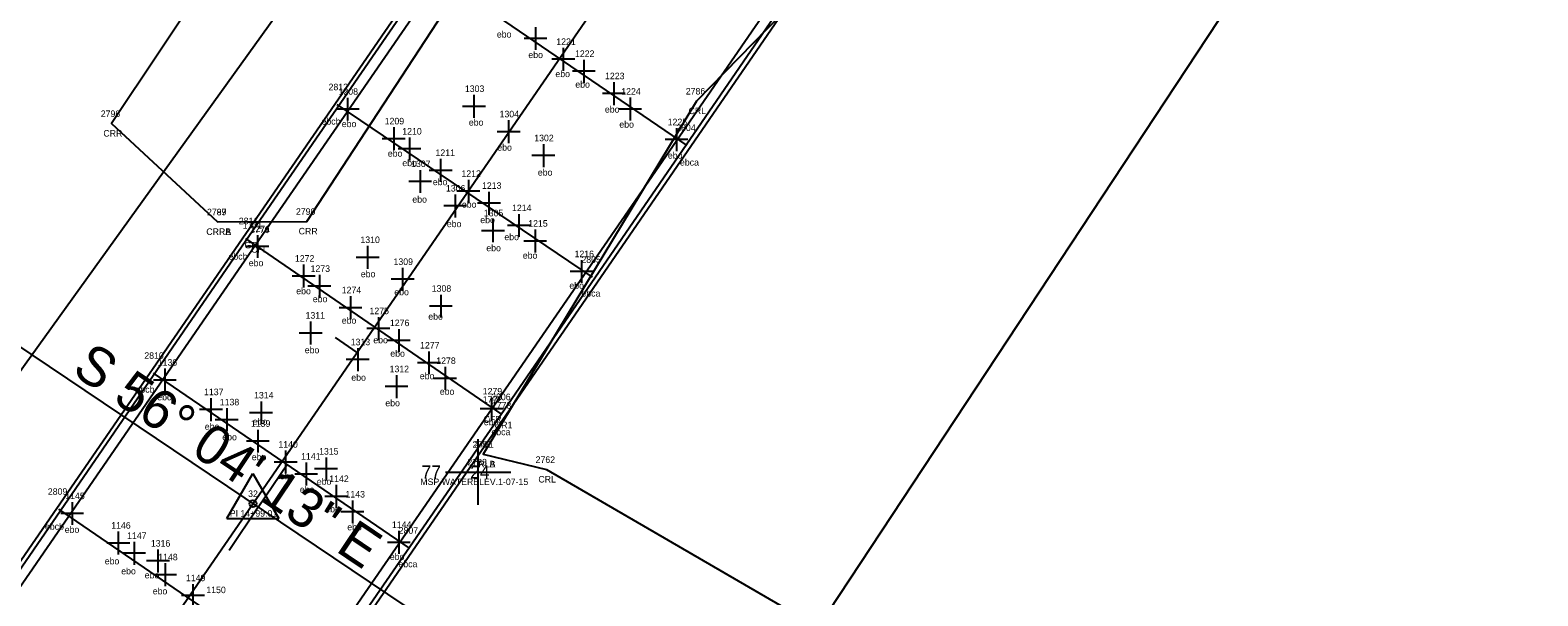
# Model space of a CAD drawing. Extents: x 2266664 to 2272542, y 716533 to 724777.
# Drawn here: x 2269061 to 2269291.5, y 720003.3 to 720089.8 of the extents above; entities that cross this region are included whole.
import ezdxf

# ---------------------------------------------------------------- set-up
doc = ezdxf.new("R2010")
doc.units = 0
for name, color, linetype in [('RD_EX_Bridge', 7, 'Continuous'), ('RD_EX_Conc', 7, 'Continuous'), ('RD_EX_Conc_txCode', 7, 'Continuous'), ('RD_EX_GuardRail', 7, 'Continuous'), ('RD_EX_GuardRail_txCode', 7, 'Continuous'), ('RD_EX_H2O', 7, 'Continuous'), ('RD_EX_H2O_txCode', 7, 'Continuous'), ('RD_EX_Misc', 7, 'Continuous'), ('RD_EX_Misc_txCode', 7, 'Continuous'), ('RD_EX_VEG', 7, 'Continuous'), ('RD_HC_Cl', 7, 'Continuous'), ('RD_HC_Data', 7, 'Continuous'), ('RD_HC_Data_Tic', 7, 'Continuous'), ('RD_HC_txCode', 7, 'Continuous'), ('RD_SMD_Locator', 7, 'Continuous')]:
    doc.layers.add(name, color=color, linetype=linetype)

msp = doc.modelspace()

# ---------------------------------------------------------------- linework, layer by layer
at = {"layer": 'RD_EX_Bridge'}
msp.add_lwpolyline([(2269005.71, 719844.75), (2269233.07, 720175.43), (2269193.18, 720202.86), (2268965.85, 719872.44), (2269005.71, 719844.75)], dxfattribs=at)
at = {"layer": 'RD_EX_Conc'}
for points in [[(2268967.59, 719871.21), (2269010.36, 719933.37), (2269052.74, 719994.95), (2269096, 720057.76), (2269138.05, 720118.85), (2269194.93, 720201.62)], [(2269004.04, 719846.24), (2269046.75, 719908.42), (2269089.1, 719970.17), (2269131.56, 720031.81), (2269174.47, 720094.11), (2269231.14, 720176.62)]]:
    msp.add_lwpolyline(points, dxfattribs=at)
at = {"layer": 'RD_EX_GuardRail'}
for points in [[(2268966.72, 719781.34), (2268981.11, 719807.65), (2269004.56, 719845.55), (2269006.56, 719847.08), (2269048.04, 719907.43), (2269090.37, 719969.18), (2269132.94, 720030.91), (2269175.81, 720093.43), (2269231.32, 720174.06), (2269253.93, 720204.36), (2269271.7, 720223.93)], [(2268919.97, 719814.14), (2268926.75, 719820.52), (2268951.58, 719851.69), (2268966.29, 719871.68), (2268967.47, 719873.87), (2269009.19, 719934.42), (2269051.44, 719995.68), (2269094.56, 720058.42), (2269136.79, 720119.9), (2269193.57, 720202.38)]]:
    msp.add_lwpolyline(points, dxfattribs=at)
at = {"layer": 'RD_EX_H2O'}
for points in [[(2269172.99, 720195.51), (2269184.44, 720188.83), (2269212.95, 720153.63), (2269214.79, 720144.82), (2269223.14, 720135.04), (2269221.7, 720125.29), (2269214.42, 720123.45), (2269202.97, 720124.92), (2269182.34, 720098.94), (2269162.9, 720078.96), (2269130.27, 720024.93)], [(2269089.67, 720060.48), (2269103.31, 720060.56), (2269128.67, 720099.37), (2269142.41, 720139.49), (2269136.61, 720156.25), (2269131.18, 720158.45), (2269103.12, 720119.97), (2269073.45, 720075.52), (2269089.67, 720060.48)], [(2269130.27, 720024.93), (2269139.94, 720022.61), (2269202.7, 719986.16), (2269249.42, 719942.61), (2269307.1, 719885.4), (2269359.22, 719846.16), (2269432.06, 719783.5), (2269460, 719761.58), (2269521.39, 719745.69)]]:
    msp.add_lwpolyline(points, dxfattribs=at)
at = {"layer": 'RD_EX_Misc'}
for p, q in [((2269161.46, 720072.18), (2269122.16, 720099.01)), ((2269138.27, 720090.28), (2269138.27, 720086.78)), ((2269140.02, 720088.53), (2269136.52, 720088.53)), ((2269142.51, 720087.09), (2269142.51, 720083.59)), ((2269144.26, 720085.34), (2269140.76, 720085.34)), ((2269147.41, 720083.51), (2269143.91, 720083.51)), ((2269145.66, 720085.26), (2269145.66, 720081.76)), ((2269150.25, 720081.85), (2269150.25, 720078.35)), ((2269109.54, 720079.47), (2269109.54, 720075.97)), ((2269128.85, 720079.9), (2269128.85, 720076.4)), ((2269152, 720080.1), (2269148.5, 720080.1)), ((2269152.73, 720079.48), (2269152.73, 720075.98)), ((2269111.29, 720077.72), (2269107.79, 720077.72)), ((2269146.96, 720052), (2269107.97, 720078.41)), ((2269130.6, 720078.15), (2269127.1, 720078.15)), ((2269154.48, 720077.73), (2269150.98, 720077.73)), ((2269116.6, 720074.95), (2269116.6, 720071.45)), ((2269135.91, 720074.27), (2269132.41, 720074.27)), ((2269134.16, 720076.02), (2269134.16, 720072.52)), ((2269159.83, 720074.81), (2269159.83, 720071.31)), ((2269118.35, 720073.2), (2269114.85, 720073.2)), ((2269120.75, 720071.63), (2269117.25, 720071.63)), ((2269119, 720073.38), (2269119, 720069.88)), ((2269139.47, 720072.36), (2269139.47, 720068.86)), ((2269161.58, 720073.06), (2269158.08, 720073.06)), ((2269123.76, 720070.1), (2269123.76, 720066.6)), ((2269141.22, 720070.61), (2269137.72, 720070.61)), ((2269120.63, 720068.41), (2269120.63, 720064.91)), ((2269125.51, 720068.35), (2269122.01, 720068.35)), ((2269128.01, 720066.91), (2269128.01, 720063.41)), ((2269122.38, 720066.66), (2269118.88, 720066.66)), ((2269125.99, 720064.67), (2269125.99, 720061.17)), ((2269129.76, 720065.16), (2269126.26, 720065.16)), ((2269131.16, 720065.08), (2269131.16, 720061.58)), ((2269127.74, 720062.92), (2269124.24, 720062.92)), ((2269132.91, 720063.33), (2269129.41, 720063.33)), ((2269131.76, 720060.88), (2269131.76, 720057.38)), ((2269135.74, 720061.67), (2269135.74, 720058.17)), ((2269133.19, 720031), (2269093.98, 720057.92)), ((2269095.77, 720058.46), (2269095.77, 720054.96)), ((2269133.51, 720059.13), (2269130.01, 720059.13)), ((2269137.49, 720059.92), (2269133.99, 720059.92)), ((2269138.22, 720059.29), (2269138.22, 720055.79)), ((2269097.52, 720056.71), (2269094.02, 720056.71)), ((2269112.6, 720056.79), (2269112.6, 720053.29)), ((2269139.97, 720057.54), (2269136.47, 720057.54)), ((2269102.82, 720053.94), (2269102.82, 720050.44)), ((2269114.35, 720055.04), (2269110.85, 720055.04)), ((2269117.95, 720053.44), (2269117.95, 720049.94)), ((2269145.32, 720054.63), (2269145.32, 720051.13)), ((2269104.57, 720052.19), (2269101.07, 720052.19)), ((2269105.23, 720052.38), (2269105.23, 720048.88)), ((2269119.7, 720051.69), (2269116.2, 720051.69)), ((2269147.07, 720052.88), (2269143.57, 720052.88)), ((2269106.98, 720050.63), (2269103.48, 720050.63)), ((2269109.99, 720049.1), (2269109.99, 720045.6)), ((2269123.8, 720049.34), (2269123.8, 720045.84)), ((2269111.74, 720047.35), (2269108.24, 720047.35)), ((2269125.55, 720047.59), (2269122.05, 720047.59)), ((2269103.89, 720045.23), (2269103.89, 720041.73)), ((2269115.99, 720044.16), (2269112.49, 720044.16)), ((2269114.24, 720045.91), (2269114.24, 720042.41)), ((2269117.38, 720044.08), (2269117.38, 720040.58)), ((2269105.64, 720043.48), (2269102.14, 720043.48)), ((2269119.13, 720042.33), (2269115.63, 720042.33)), ((2269112.84, 720039.41), (2269109.34, 720039.41)), ((2269111.09, 720041.16), (2269111.09, 720037.66)), ((2269121.97, 720040.66), (2269121.97, 720037.16)), ((2269119.02, 720010.58), (2269079.84, 720037.33)), ((2269081.6, 720038.04), (2269081.6, 720034.54)), ((2269117.02, 720037.03), (2269117.02, 720033.53)), ((2269123.72, 720038.91), (2269120.22, 720038.91)), ((2269124.45, 720038.29), (2269124.45, 720034.79)), ((2269083.35, 720036.29), (2269079.85, 720036.29)), ((2269118.77, 720035.28), (2269115.27, 720035.28)), ((2269126.2, 720036.54), (2269122.7, 720036.54)), ((2269088.65, 720033.52), (2269088.65, 720030.02)), ((2269096.3, 720033.02), (2269096.3, 720029.52)), ((2269131.55, 720033.63), (2269131.55, 720030.13)), ((2269090.4, 720031.77), (2269086.9, 720031.77)), ((2269092.81, 720030.21), (2269089.31, 720030.21)), ((2269091.06, 720031.96), (2269091.06, 720028.46)), ((2269098.05, 720031.27), (2269094.55, 720031.27)), ((2269133.3, 720031.88), (2269129.8, 720031.88)), ((2269095.82, 720028.68), (2269095.82, 720025.18)), ((2269097.57, 720026.93), (2269094.07, 720026.93)), ((2269100.07, 720025.49), (2269100.07, 720021.99)), ((2269129.5, 720017.22), (2269129.5, 720027.22)), ((2269101.82, 720023.74), (2269098.32, 720023.74)), ((2269103.21, 720023.66), (2269103.21, 720020.16)), ((2269106.24, 720024.43), (2269106.24, 720020.93)), ((2269104.96, 720021.91), (2269101.46, 720021.91)), ((2269107.99, 720022.68), (2269104.49, 720022.68)), ((2269124.5, 720022.22), (2269134.5, 720022.22)), ((2269109.55, 720018.49), (2269106.05, 720018.49)), ((2269107.8, 720020.24), (2269107.8, 720016.74)), ((2269104.26, 719989.95), (2269065.38, 720016.53)), ((2269067.43, 720017.62), (2269067.43, 720014.12)), ((2269110.28, 720017.87), (2269110.28, 720014.37)), ((2269069.18, 720015.87), (2269065.68, 720015.87)), ((2269112.03, 720016.12), (2269108.53, 720016.12)), ((2269074.48, 720013.1), (2269074.48, 720009.6)), ((2269117.38, 720013.21), (2269117.38, 720009.71)), ((2269076.23, 720011.35), (2269072.73, 720011.35)), ((2269078.64, 720009.79), (2269075.14, 720009.79)), ((2269076.89, 720011.54), (2269076.89, 720008.04)), ((2269080.55, 720010.36), (2269080.55, 720006.86)), ((2269119.13, 720011.46), (2269115.63, 720011.46)), ((2269082.3, 720008.61), (2269078.8, 720008.61)), ((2269081.65, 720008.26), (2269081.65, 720004.76)), ((2269083.4, 720006.51), (2269079.9, 720006.51)), ((2269085.9, 720005.07), (2269085.9, 720001.57)), ((2269087.65, 720003.32), (2269084.15, 720003.32))]:
    msp.add_line(p, q, dxfattribs=at)
at = {"layer": 'RD_EX_VEG'}
for points in [[(2268819.78, 719716.8), (2268871.54, 719776.21), (2269193.85, 720224.65), (2269408.57, 720538.5), (2269589.67, 720791.77), (2270047.56, 721479.8), (2270363.13, 721951.09), (2270746.65, 722498.38), (2270919.94, 722752.82), (2271017.26, 722923.37)], [(2268988.31, 719705.64), (2269316.7, 720203.55), (2269323.19, 720195.95)]]:
    msp.add_lwpolyline(points, dxfattribs=at)
at = {"layer": 'RD_HC_Cl'}
for p, q in [((2267342.91, 717471.2), (2272360.46, 724762.59)), ((2269054.71, 720044.54), (2269123.76, 719998.09))]:
    msp.add_line(p, q, dxfattribs=at)
at = {"layer": 'RD_HC_Data'}
for p, q in [((2269091.09, 720015.1), (2269095.07, 720021.98)), ((2269095.07, 720021.98), (2269099.03, 720015.1)), ((2269091.09, 720015.1), (2269099.03, 720015.1))]:
    msp.add_line(p, q, dxfattribs=at)
msp.add_circle((2269095.06, 720017.39), 0.529, dxfattribs=at)
at = {"layer": 'RD_HC_Data_Tic'}
for p, q in [((2269110.98, 720040.52), (2269107.68, 720042.79)), ((2269095.89, 720016.84), (2269100.35, 720023.47)), ((2269095.89, 720016.84), (2269091.42, 720010.2))]:
    msp.add_line(p, q, dxfattribs=at)
at = {"layer": 'RD_SMD_Locator'}
for centre in [(2269162.9, 720078.96), (2269073.45, 720075.52), (2269089.67, 720060.48), (2269089.67, 720060.48), (2269103.31, 720060.56), (2269094.56, 720058.42), (2269096, 720057.76), (2269131.56, 720031.81), (2269132.94, 720030.91), (2269130.27, 720024.93), (2269130.27, 720024.93), (2269139.94, 720022.61), (2269095.06, 720017.39)]:
    msp.add_circle(centre, 0.001, dxfattribs=at)

# ---------------------------------------------------------------- texts
at = {"layer": 'RD_EX_Conc_txCode'}
for s, p in [('1770', (2269094.62, 720058.76)), ('CFL', (2269094.8, 720055.76)), ('1772', (2269130.22, 720032.81)), ('CFR', (2269130.33, 720029.81))]:
    msp.add_text(s, height=1, dxfattribs=at).set_placement(p)
at = {"layer": 'RD_EX_GuardRail_txCode'}
for s, p in [('1771', (2269093.5, 720059.42)), ('GR', (2269093.78, 720056.42)), ('1773', (2269131.59, 720031.91)), ('GR1', (2269131.99, 720028.91))]:
    msp.add_text(s, height=1, dxfattribs=at).set_placement(p)
at = {"layer": 'RD_EX_H2O_txCode'}
for s, p in [('2786', (2269161.25, 720079.96)), ('2796', (2269071.8, 720076.52)), ('CRL', (2269161.67, 720076.96)), ('CRR', (2269072.2, 720073.52)), ('2789', (2269088.04, 720061.48)), ('2797', (2269088.04, 720061.48)), ('2790', (2269101.64, 720061.56)), ('CRRA', (2269087.93, 720058.48)), ('CRRB', (2269087.95, 720058.48)), ('CRR', (2269102.06, 720058.56)), ('2787', (2269128.64, 720025.93)), ('2761', (2269128.9, 720025.93)), ('CRLA', (2269128.55, 720022.93)), ('CRLB', (2269128.57, 720022.93)), ('2762', (2269138.29, 720023.61)), ('CRL', (2269138.71, 720020.61))]:
    msp.add_text(s, height=1, dxfattribs=at).set_placement(p)
at = {"layer": 'RD_EX_Misc_txCode'}
for s, height, p in [('ebo', 1, (2269132.36, 720088.67)), ('1221', 1, (2269141.45, 720087.54)), ('ebo', 1, (2269137.18, 720085.53)), ('1222', 1, (2269144.31, 720085.71)), ('ebo', 1, (2269141.31, 720082.62)), ('1223', 1, (2269148.9, 720082.3)), ('2812', 1, (2269106.63, 720080.61)), ('1208', 1, (2269108.16, 720079.92)), ('1303', 1, (2269127.47, 720080.35)), ('ebo', 1, (2269144.36, 720081.01)), ('1224', 1, (2269151.38, 720079.93)), ('ebcb', 1, (2269105.55, 720075.36)), ('1209', 1, (2269115.21, 720075.39)), ('ebo', 1, (2269128.08, 720075.2)), ('1304', 1, (2269132.78, 720076.47)), ('ebo', 1, (2269148.88, 720077.19)), ('1225', 1, (2269158.48, 720075.26)), ('ebo', 1, (2269108.65, 720074.97)), ('1210', 1, (2269117.9, 720073.83)), ('1302', 1, (2269138.08, 720072.81)), ('ebo', 1, (2269151.09, 720074.89)), ('2804', 1, (2269159.79, 720074.38)), ('1211', 1, (2269122.98, 720070.55)), ('ebo', 1, (2269132.43, 720071.37)), ('ebo', 1, (2269115.69, 720070.45)), ('ebo', 1, (2269117.91, 720069)), ('1307', 1, (2269119.25, 720068.86)), ('ebo', 1, (2269158.51, 720070.15)), ('ebca', 1, (2269160.36, 720069.09)), ('ebo', 1, (2269122.57, 720066.09)), ('1212', 1, (2269126.95, 720067.36)), ('ebo', 1, (2269138.63, 720067.55)), ('1306', 1, (2269124.58, 720065.12)), ('1213', 1, (2269130.09, 720065.53)), ('ebo', 1, (2269119.44, 720063.42)), ('ebo', 1, (2269127.01, 720062.65)), ('1305', 1, (2269130.37, 720061.33)), ('1214', 1, (2269134.68, 720062.12)), ('2811', 1, (2269092.91, 720060.12)), ('ebo', 1, (2269124.71, 720059.67)), ('ebo', 1, (2269129.83, 720060.28)), ('1215', 1, (2269137.16, 720059.74)), ('1271', 1, (2269094.71, 720058.91)), ('1310', 1, (2269111.5, 720057.24)), ('ebo', 1, (2269133.51, 720057.68)), ('ebcb', 1, (2269091.33, 720054.7)), ('1272', 1, (2269101.48, 720054.39)), ('ebo', 1, (2269130.75, 720055.99)), ('ebo', 1, (2269136.33, 720054.85)), ('1216', 1, (2269144.24, 720055.08)), ('ebo', 1, (2269094.43, 720053.7)), ('1273', 1, (2269103.88, 720052.83)), ('1309', 1, (2269116.56, 720053.89)), ('2805', 1, (2269145.29, 720054.2)), ('ebo', 1, (2269111.56, 720052.01)), ('1308', 1, (2269122.41, 720049.79)), ('ebo', 1, (2269143.45, 720050.25)), ('ebo', 1, (2269101.69, 720049.41)), ('ebo', 1, (2269104.22, 720048.19)), ('1274', 1, (2269108.64, 720049.55)), ('ebo', 1, (2269116.68, 720049.26)), ('ebca', 1, (2269145.29, 720049.05)), ('1311', 1, (2269103.11, 720045.68)), ('1275', 1, (2269112.89, 720046.36)), ('ebo', 1, (2269121.88, 720045.51)), ('ebo', 1, (2269108.65, 720044.9)), ('1276', 1, (2269116.01, 720044.53)), ('1313', 1, (2269110.02, 720041.61)), ('ebo', 1, (2269113.47, 720041.91)), ('1277', 1, (2269120.62, 720041.11)), ('2810', 1, (2269078.46, 720039.53)), ('1136', 1, (2269080.51, 720038.49)), ('ebo', 1, (2269102.99, 720040.38)), ('ebo', 1, (2269116.07, 720039.85)), ('1278', 1, (2269123.1, 720038.74)), ('ebo', 1, (2269110.11, 720036.18)), ('1312', 1, (2269115.96, 720037.48)), ('ebo', 1, (2269120.58, 720036.41)), ('ebcb', 1, (2269077.11, 720034.35)), ('1137', 1, (2269087.59, 720033.97)), ('ebo', 1, (2269123.64, 720034.03)), ('1279', 1, (2269130.2, 720034.08)), ('ebo', 1, (2269080.44, 720033.19)), ('1138', 1, (2269090, 720032.41)), ('1314', 1, (2269095.24, 720033.47)), ('ebo', 1, (2269115.31, 720032.27)), ('2806', 1, (2269131.49, 720033.2)), ('1139', 1, (2269094.76, 720029.13)), ('ebo', 1, (2269095.04, 720029.44)), ('ebo', 1, (2269130.37, 720029.37)), ('ebo', 1, (2269087.7, 720028.68)), ('ebo', 1, (2269090.38, 720027.07)), ('ebca', 1, (2269131.53, 720027.85)), ('1140', 1, (2269098.96, 720025.94)), ('1315', 1, (2269105.18, 720024.88)), ('ebo', 1, (2269094.89, 720024.01)), ('1141', 1, (2269102.43, 720024.11)), ('77      24', 2, (2269120.85, 720021.22)), ('2788', 1, (2269127.87, 720023.22)), ('ebo', 1, (2269099.17, 720021.1)), ('ebo', 1, (2269104.83, 720020.26)), ('1142', 1, (2269106.74, 720020.69)), ('MSP WATERELEV.1-07-15', 1, (2269120.66, 720020.22)), ('2809', 1, (2269063.71, 720018.73)), ('1145', 1, (2269066.37, 720018.07)), ('ebo', 1, (2269102.23, 720019.04)), ('1143', 1, (2269109.22, 720018.32)), ('ebo', 1, (2269106.13, 720016.05)), ('ebcb', 1, (2269063.27, 720013.39)), ('ebo', 1, (2269066.29, 720012.91)), ('1146', 1, (2269073.4, 720013.55)), ('ebo', 1, (2269109.49, 720013.3)), ('1144', 1, (2269116.32, 720013.66)), ('1147', 1, (2269075.83, 720011.99)), ('1316', 1, (2269079.46, 720010.81)), ('2807', 1, (2269117.35, 720012.78)), ('1148', 1, (2269080.59, 720008.71)), ('ebo', 1, (2269115.99, 720008.78)), ('ebo', 1, (2269072.41, 720008.09)), ('ebo', 1, (2269074.93, 720006.56)), ('ebo', 1, (2269078.52, 720005.95)), ('ebca', 1, (2269117.31, 720007.65)), ('1149', 1, (2269084.83, 720005.52)), ('1150', 1, (2269087.94, 720003.69)), ('ebo', 1, (2269079.75, 720003.5))]:
    msp.add_text(s, height=height, dxfattribs=at).set_placement(p)
at = {"layer": 'RD_HC_Data'}
msp.add_text('S 56%%d 04\' 13" E', height=6, rotation=326.0703, dxfattribs=at).set_placement((2269067.19, 720037.35))
at = {"layer": 'RD_HC_txCode'}
for s, p in [('32', (2269094.33, 720018.39)), ('PI 14+99.01', (2269091.53, 720015.39))]:
    msp.add_text(s, height=1, dxfattribs=at).set_placement(p)

doc.saveas('drawing.dxf')
